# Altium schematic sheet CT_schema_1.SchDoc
size 722 x 518 mm
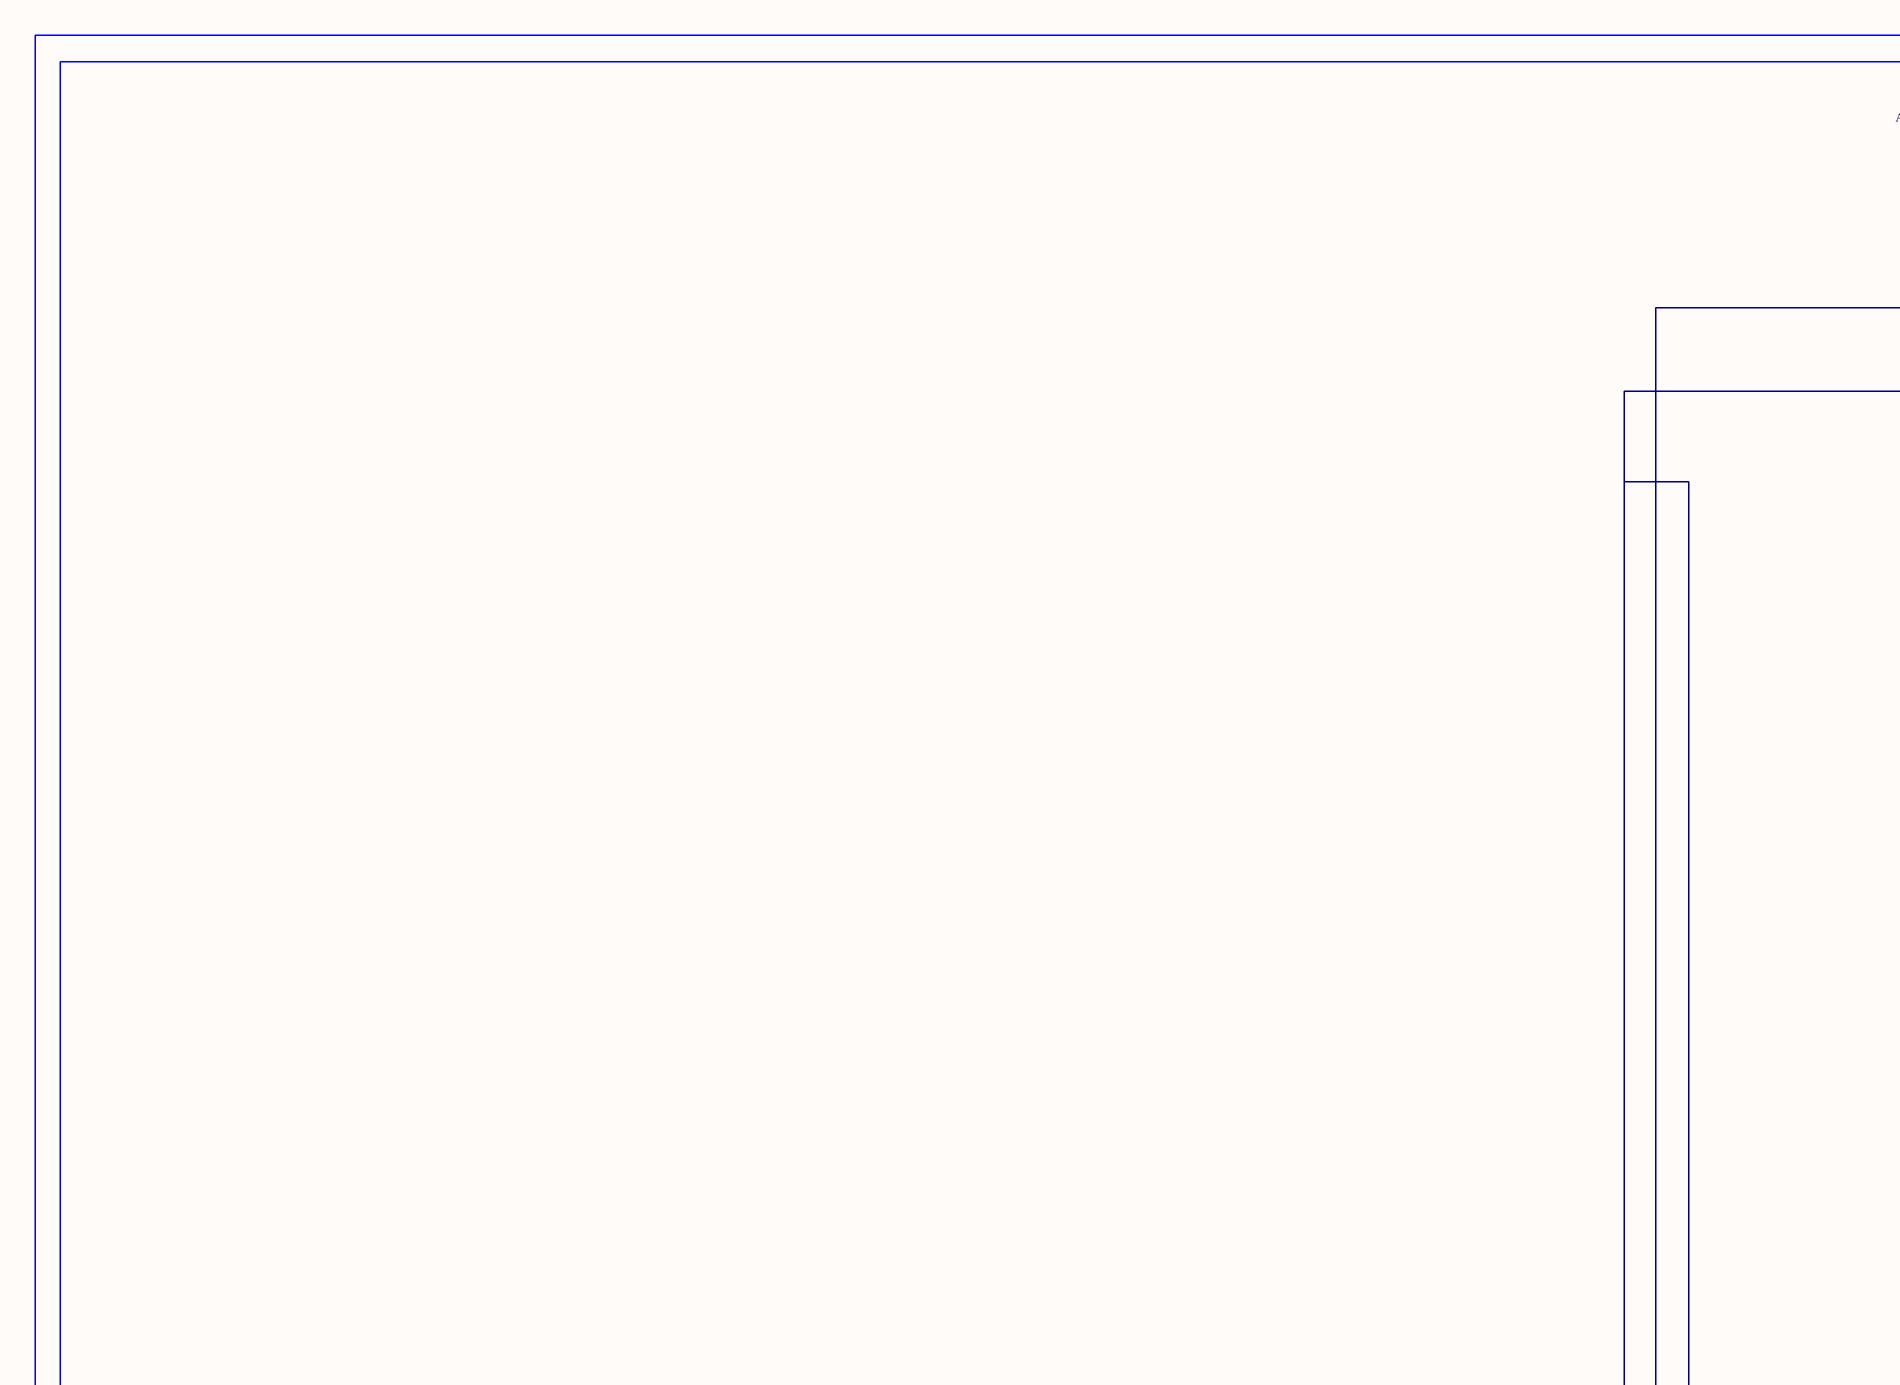
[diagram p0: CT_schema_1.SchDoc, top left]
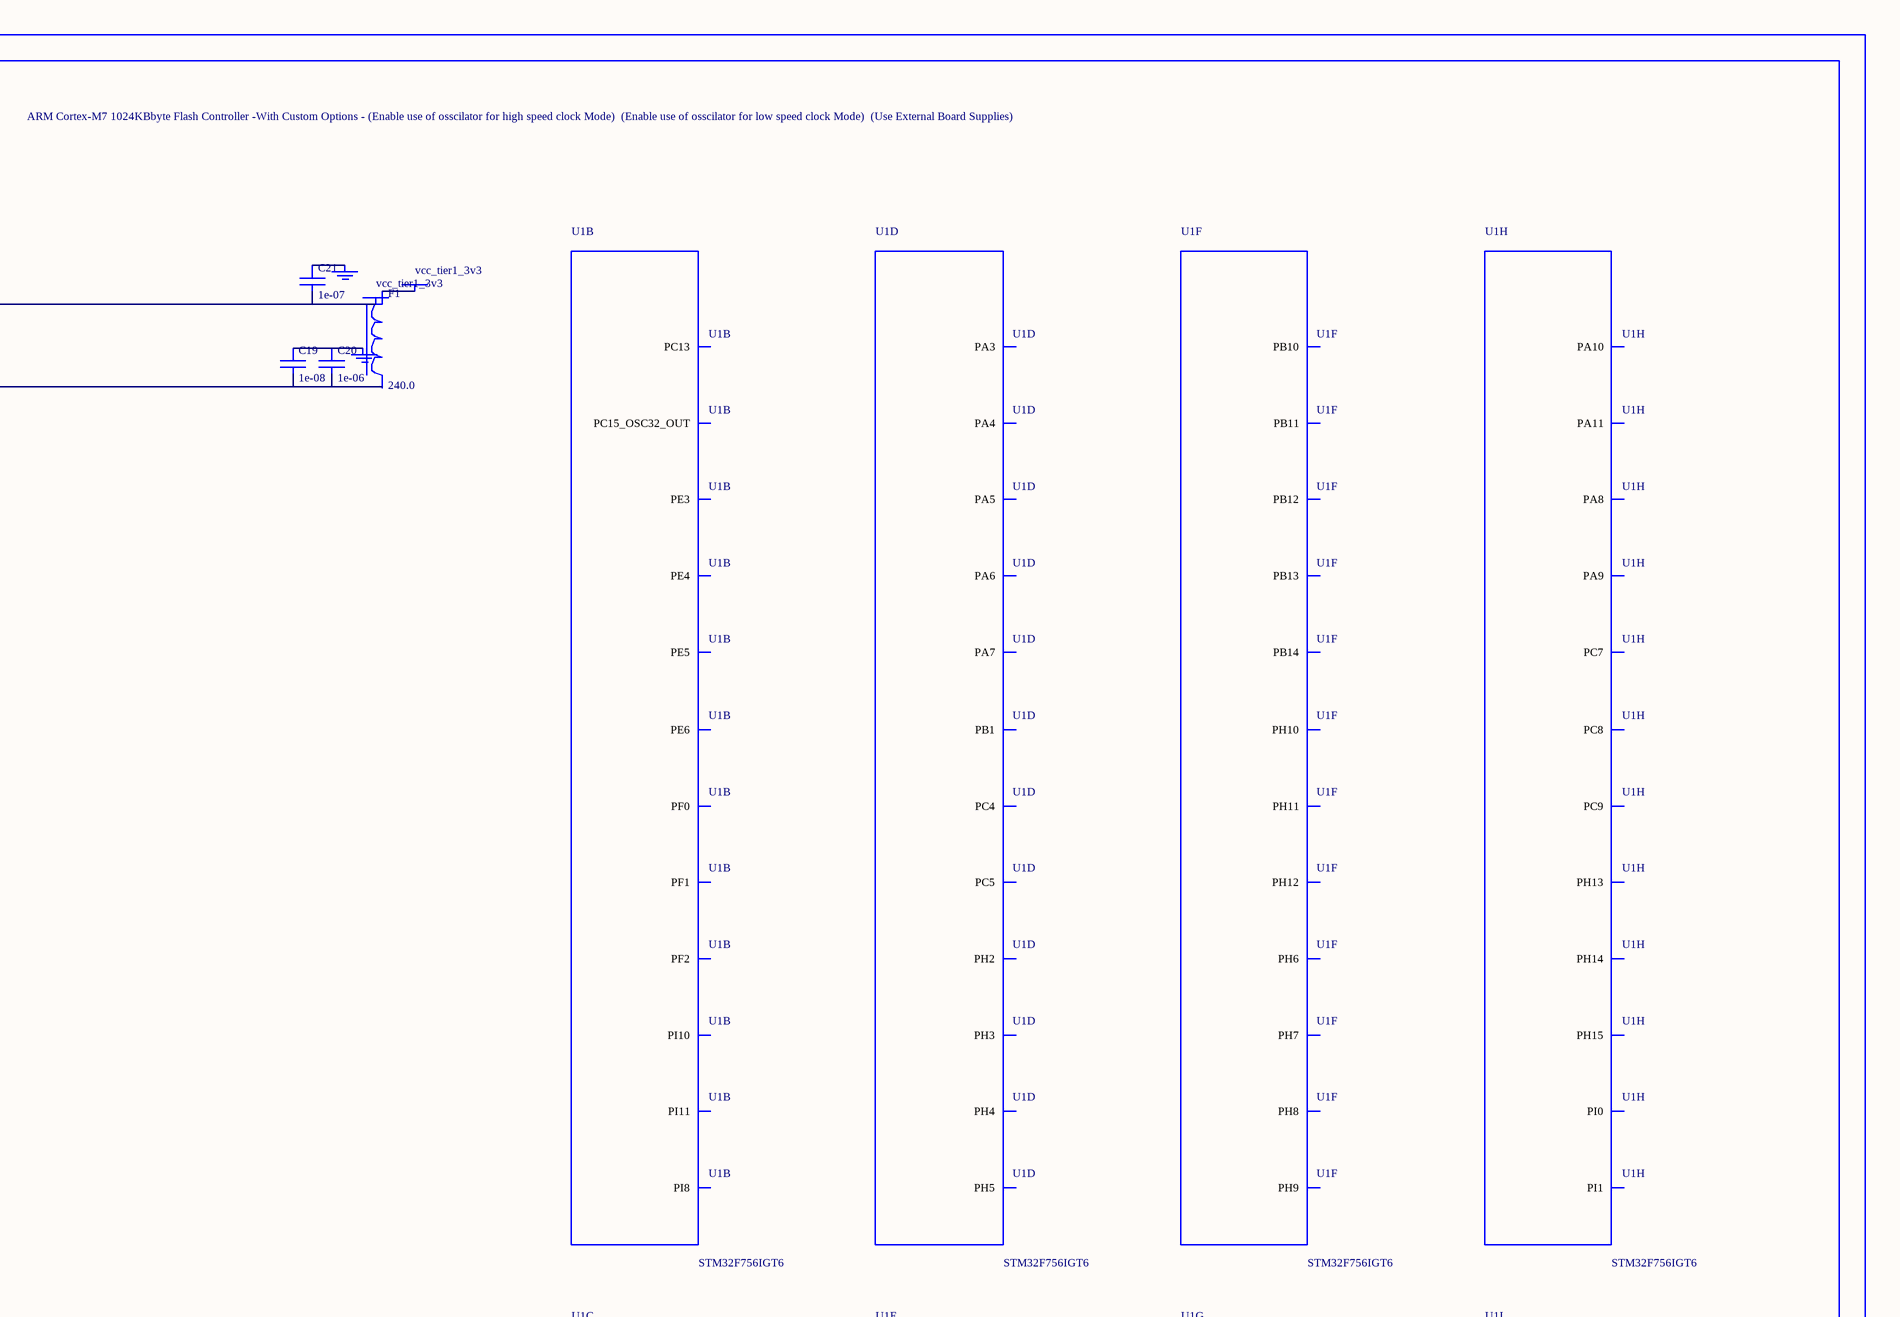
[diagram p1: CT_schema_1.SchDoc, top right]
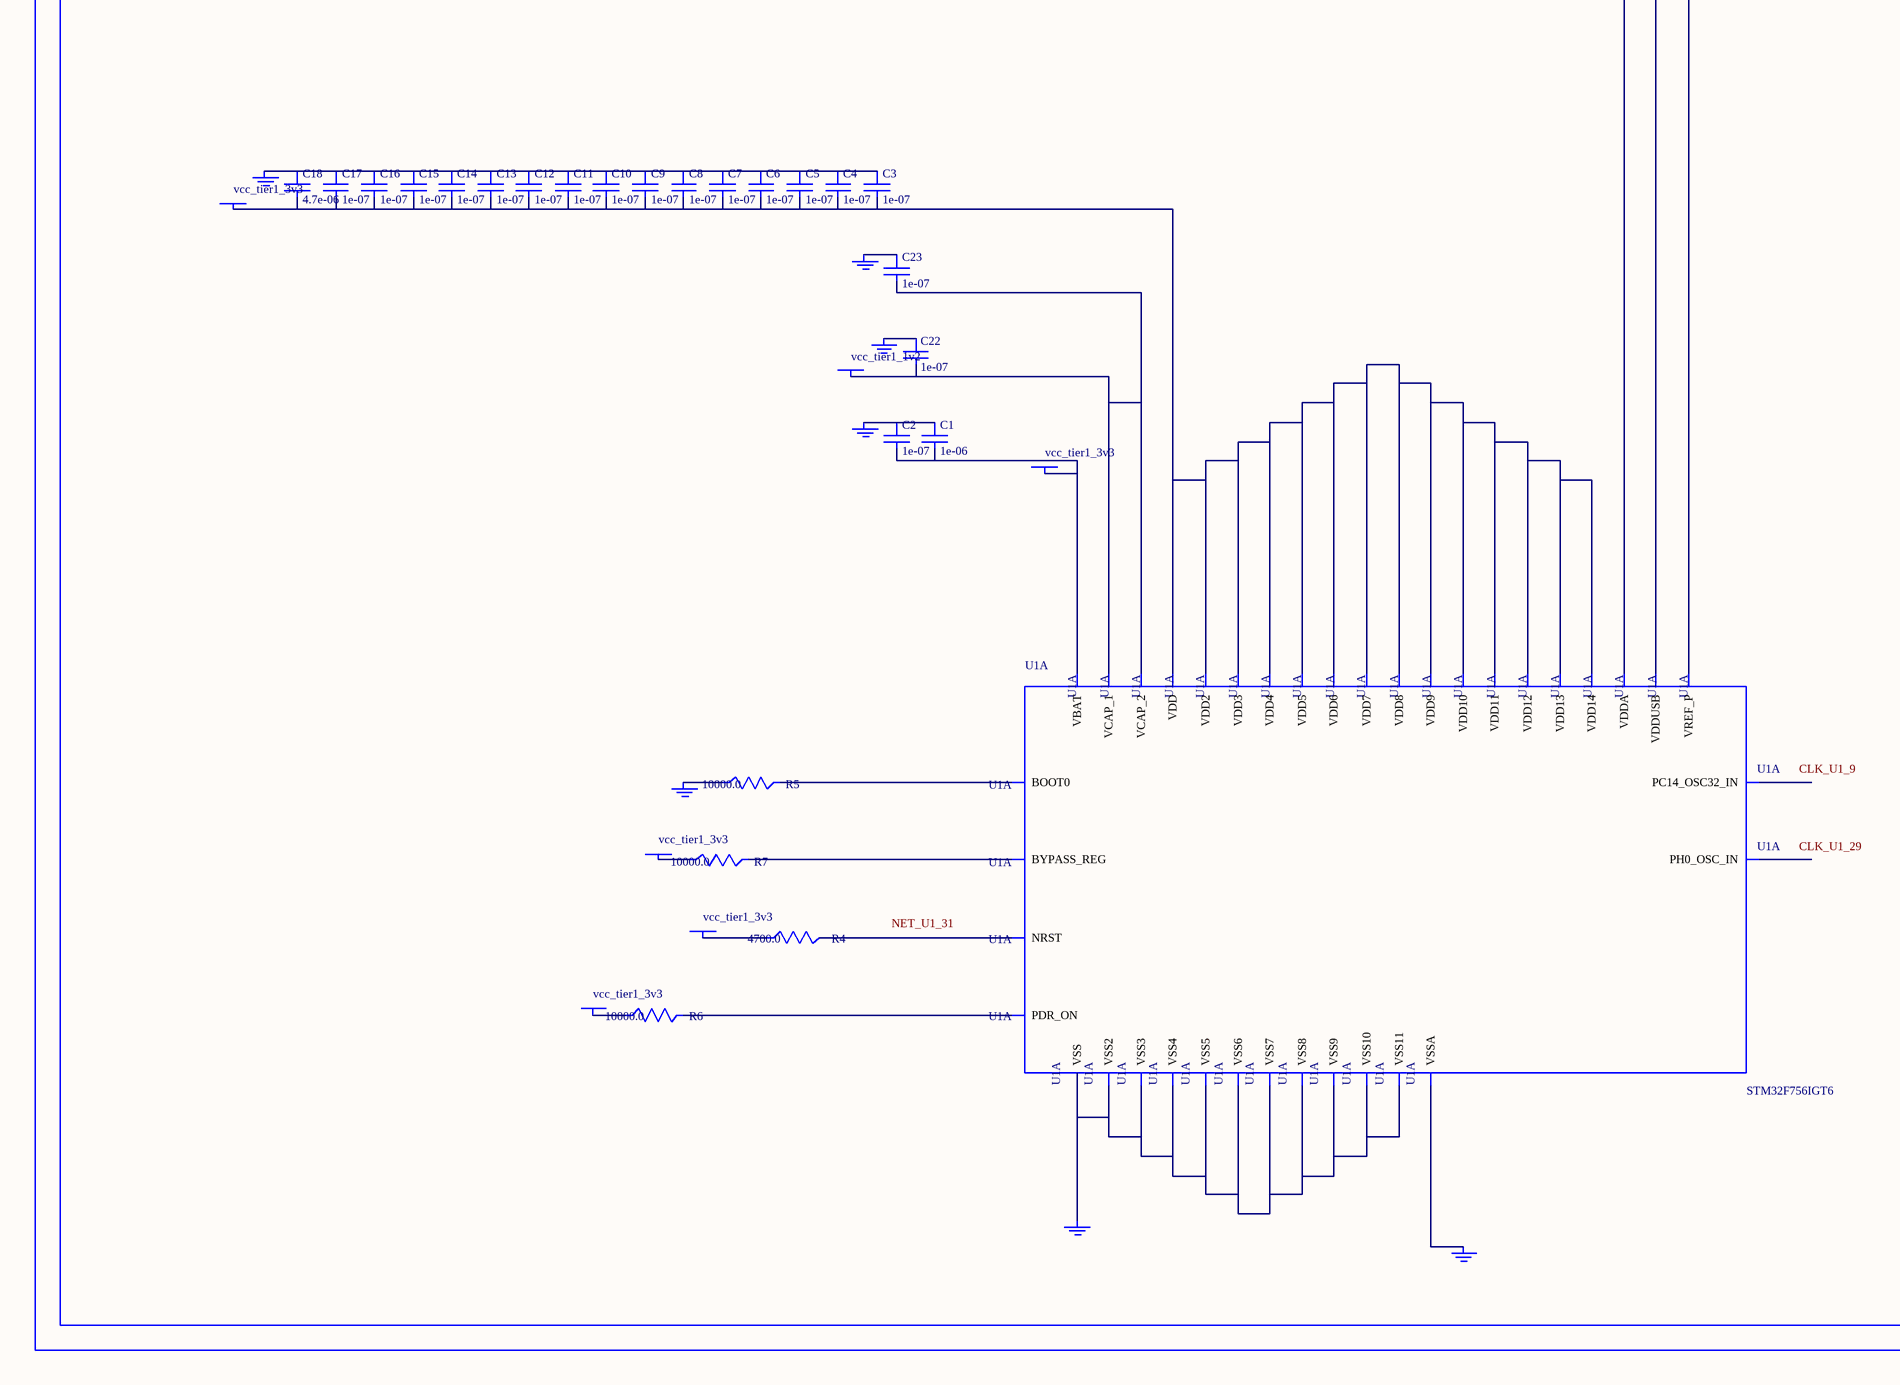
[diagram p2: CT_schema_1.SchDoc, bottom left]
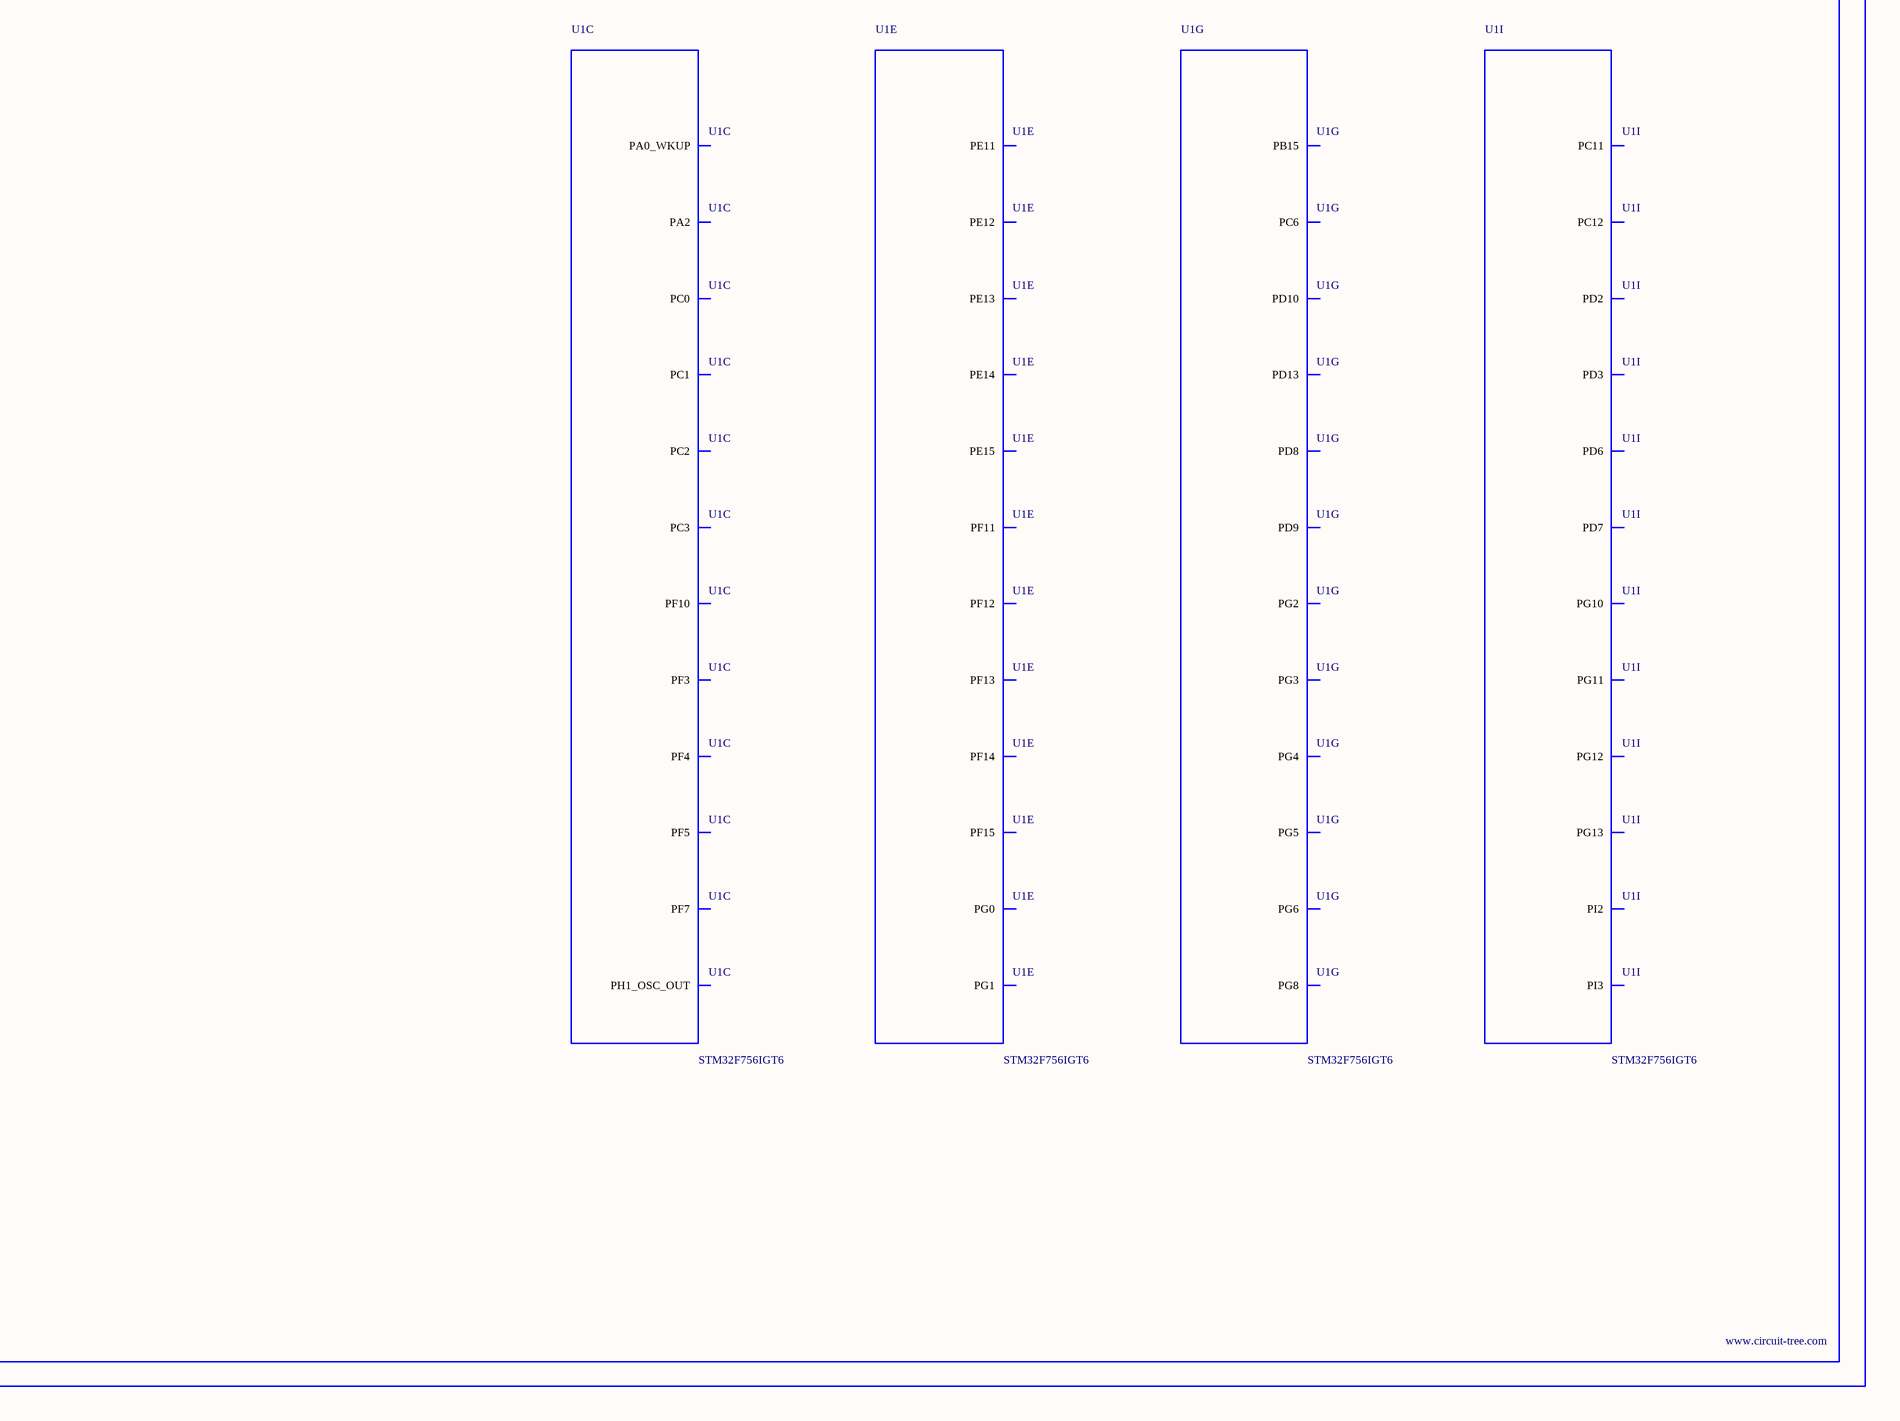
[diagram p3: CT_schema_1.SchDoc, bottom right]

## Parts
BORDER0  (no value)
C1  1e-06  [C0603]
C2  1e-07  [C0603]
C3  1e-07  [C0603]
C4  1e-07  [C0603]
C5  1e-07  [C0603]
C6  1e-07  [C0603]
C7  1e-07  [C0603]
C8  1e-07  [C0603]
C9  1e-07  [C0603]
C10  1e-07  [C0603]
C11  1e-07  [C0603]
C12  1e-07  [C0603]
C13  1e-07  [C0603]
C14  1e-07  [C0603]
C15  1e-07  [C0603]
C16  1e-07  [C0603]
C17  1e-07  [C0603]
C18  4.7e-06  [C0603]
C19  1e-08  [C0603]
C20  1e-06  [C0603]
C21  1e-07  [C0603]
C22  1e-07  [C0603]
C23  1e-07  [C0603]
F1  240.0  [L0603]
GND_INSTANCE_0_0  (no value)
GND_INSTANCE_0_1  (no value)
GND_INSTANCE_0_2  (no value)
GND_INSTANCE_0_3  (no value)
GND_INSTANCE_0_4  (no value)
GND_INSTANCE_0_5  (no value)
GND_INSTANCE_0_6  (no value)
GND_INSTANCE_0_7  (no value)
GND_INSTANCE_0_8  (no value)
POWER_INSTANCE_0_0  vcc_tier1_3v3
POWER_INSTANCE_0_1  vcc_tier1_3v3
POWER_INSTANCE_0_2  vcc_tier1_3v3
POWER_INSTANCE_0_3  vcc_tier1_3v3
POWER_INSTANCE_0_4  vcc_tier1_1v2
POWER_INSTANCE_0_5  vcc_tier1_3v3
POWER_INSTANCE_0_6  vcc_tier1_3v3
POWER_INSTANCE_0_7  vcc_tier1_3v3
R4  4700.0  [R0603]
R5  10000.0  [R0603]
R6  10000.0  [R0603]
R7  10000.0  [R0603]
U1  STM32F756IGT6  [LQFP176]  (parts A,B,C,D,E,F,G,H,I of 14)

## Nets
NetC1_1: C1.1 C2.1 GND_INSTANCE_0_0.0(GND)
NetC1_2: C1.2 C2.2 POWER_INSTANCE_0_0.0(PWR) U1.6(VBAT)
NetC3_1: C3.1 C4.1 C5.1 C6.1 C7.1 C8.1 C9.1 C10.1 C11.1 C12.1 C13.1 C14.1 C15.1 C16.1 C17.1 C18.1 GND_INSTANCE_0_1.0(GND)
NetC3_2: C3.2 C4.2 C5.2 C6.2 C7.2 C8.2 C9.2 C10.2 C11.2 C12.2 C13.2 C14.2 C15.2 C16.2 C17.2 C18.2 POWER_INSTANCE_0_1.0(PWR) U1.15(VDD) U1.23(VDD2) U1.36(VDD3) U1.49(VDD4) U1.62(VDD5) U1.72(VDD6) U1.82(VDD7) U1.91(VDD8) U1.103(VDD9) U1.127(VDD10) U1.136(VDD11) U1.149(VDD12) U1.159(VDD13) U1.172(VDD14)
NetC19_1: C19.1 C20.1 GND_INSTANCE_0_3.0(GND)
NetC19_2: C19.2 C20.2 U1.38(VREF_P) U1.39(VDDA)
NetC21_1: C21.1 GND_INSTANCE_0_5.0(GND)
NetC21_2: C21.2 POWER_INSTANCE_0_5.0(PWR) U1.114(VDDUSB)
NetC22_1: C22.1 GND_INSTANCE_0_4.0(GND)
NetC22_2: C22.2 C23.2 POWER_INSTANCE_0_4.0(PWR) U1.81(VCAP_1) U1.125(VCAP_2)
NetC23_1: C23.1 GND_INSTANCE_0_6.0(GND)
NetF1_1: F1.1 POWER_INSTANCE_0_2.0(PWR)
NetGND_INSTANCE_0_2_0: GND_INSTANCE_0_2.0(GND) U1.37(VSSA)
NetGND_INSTANCE_0_7_0: GND_INSTANCE_0_7.0(GND) R5.1
NetGND_INSTANCE_0_8_0: GND_INSTANCE_0_8.0(GND) U1.14(VSS) U1.22(VSS2) U1.61(VSS3) U1.71(VSS4) U1.90(VSS5) U1.102(VSS6) U1.113(VSS7) U1.126(VSS8) U1.135(VSS9) U1.148(VSS10) U1.158(VSS11)
NetPOWER_INSTANCE_0_3_0: POWER_INSTANCE_0_3.0(PWR) R7.1
NetPOWER_INSTANCE_0_6_0: POWER_INSTANCE_0_6.0(PWR) R6.1
NetPOWER_INSTANCE_0_7_0: POWER_INSTANCE_0_7.0(PWR) R4.1
NetR4_2: R4.2 U1.31(NRST)
NetR5_2: R5.2 U1.166(BOOT0)
NetR6_2: R6.2 U1.171(PDR_ON)
NetR7_2: R7.2 U1.48(BYPASS_REG)

Not connected (* = marked no-connect by the designer): F1 2; U1 2(PE3) 3(PE4) 4(PE5) 5(PE6) 7(PI8) 8(PC13) 9(PC14_OSC32_IN) 10(PC15_OSC32_OUT) 12(PI10) 13(PI11) 16(PF0) 17(PF1) 18(PF2) 19(PF3) 20(PF4) 21(PF5) 25(PF7) 28(PF10) 29(PH0_OSC_IN) 30(PH1_OSC_OUT) 32(PC0) 33(PC1) 34(PC2) 35(PC3) 40(PA0_WKUP) 42(PA2) 43(PH2) 44(PH3) 45(PH4) 46(PH5) 47(PA3) 50(PA4) 51(PA5) 52(PA6) 53(PA7) 54(PC4) 55(PC5) 57(PB1) 59(PF11) 60(PF12) 63(PF13) 64(PF14) 65(PF15) 66(PG0) 67(PG1) 74(PE11) 75(PE12) 76(PE13) 77(PE14) 78(PE15) 79(PB10) 80(PB11) 83(PH6) 84(PH7) 85(PH8) 86(PH9) 87(PH10) 88(PH11) 89(PH12) 92(PB12) 93(PB13) 94(PB14) 95(PB15) 96(PD8) 97(PD9) 98(PD10) 101(PD13) 106(PG2) 107(PG3) 108(PG4) 109(PG5) 110(PG6) 112(PG8) 115(PC6) 116(PC7) 117(PC8) 118(PC9) 119(PA8) 120(PA9) 121(PA10) 122(PA11) 128(PH13) 129(PH14) 130(PH15) 131(PI0) 132(PI1) 133(PI2) 134(PI3) 140(PC11) 141(PC12) 144(PD2) 145(PD3) 150(PD6) 151(PD7) 153(PG10) 154(PG11) 155(PG12) 156(PG13)

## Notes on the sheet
- Labels drawn without touching a wire or pin: CLK_U1_9, CLK_U1_29, NET_U1_31

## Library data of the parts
BORDER0 = BORDER_PAGE0
C1 C20 = C0603C105K3RACTU
C2-C17 C21-C23 = 06035C104K4Z2A
C18 = GRM188R6YA475KE15D
C19 = 06035C103K4Z2A
F1 = Z0603C241ASMST
GND_INSTANCE_0_0-GND_INSTANCE_0_8 = GND
POWER_INSTANCE_0_0-POWER_INSTANCE_0_7 = PWR
R4 = RC0603JR-074K7L
R5-R7 = RC0603JR-0710KL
